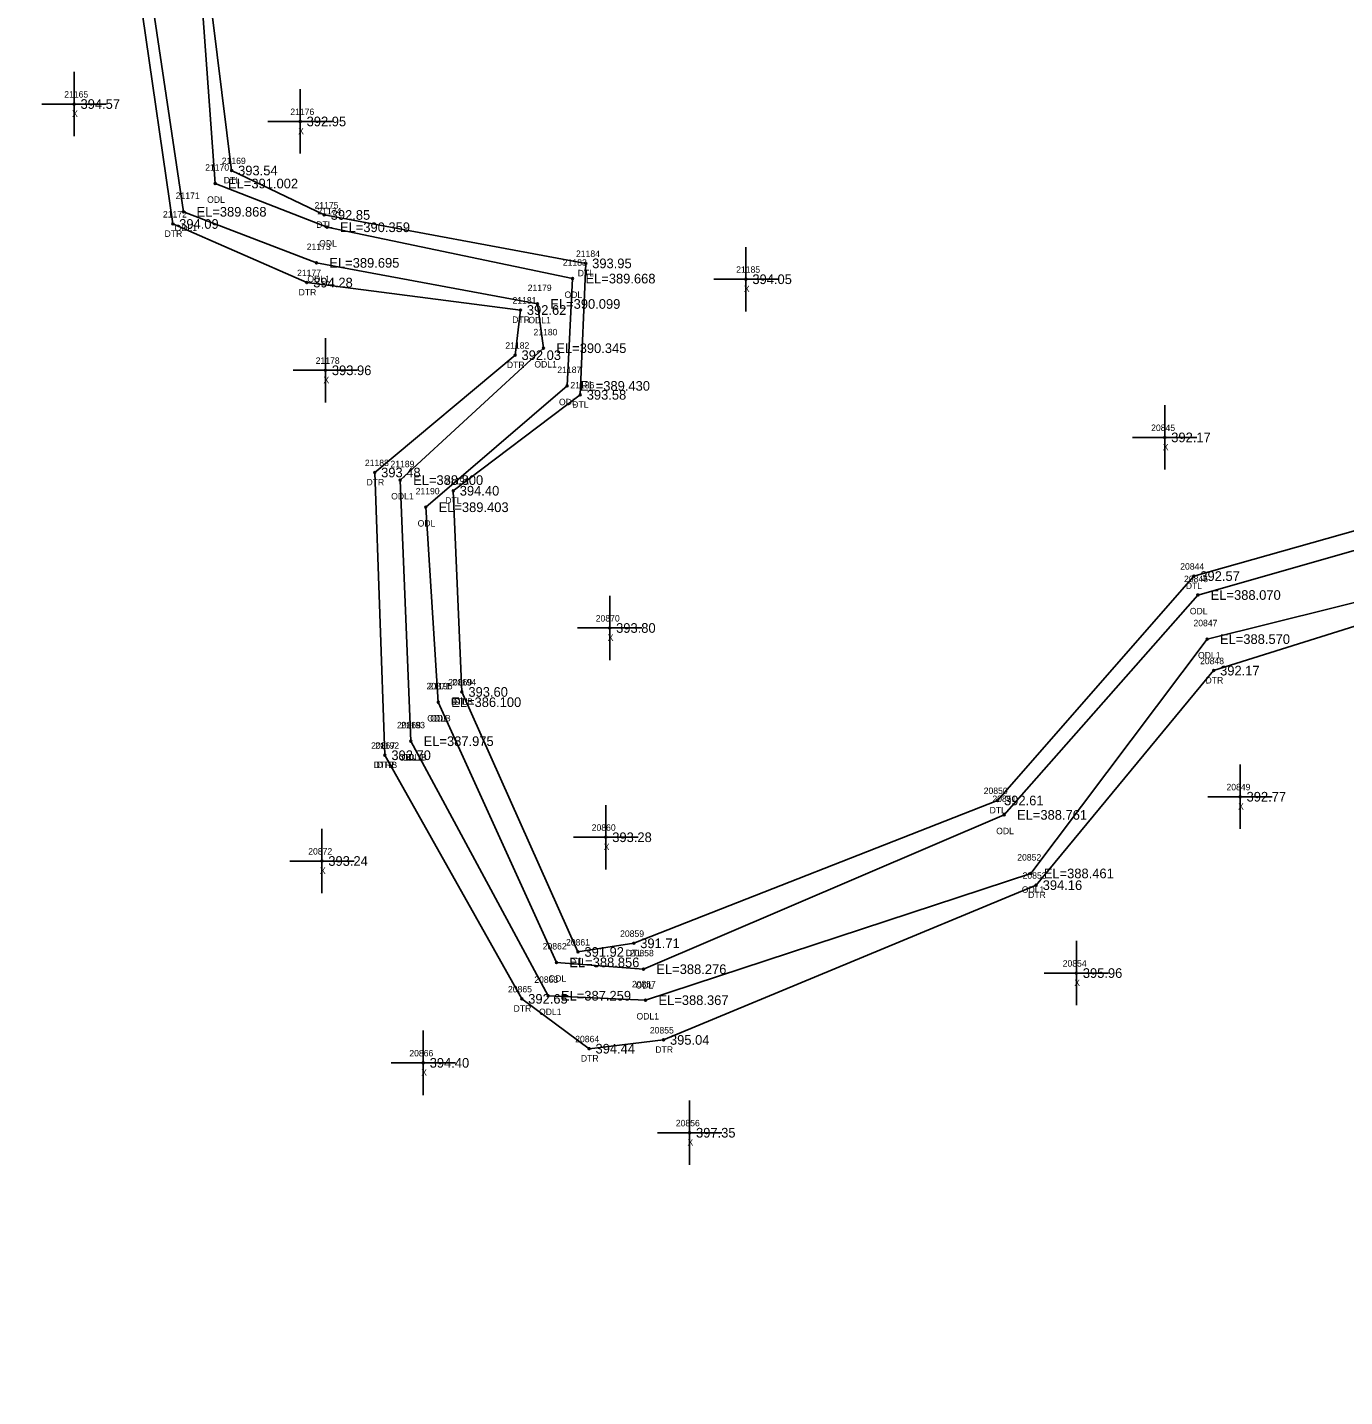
# Model space of a CAD drawing. Extents: x 2186623 to 2187804, y 1079975 to 1082766.
# Drawn here: x 2186677.8 to 2186882.3, y 1082143.2 to 1082355.8 of the extents above; entities that cross this region are included whole.
import ezdxf

# ---------------------------------------------------------------- set-up
doc = ezdxf.new("R2010")
doc.units = 0
for name, color, linetype in [('RD_EX_H2O', 7, 'Continuous'), ('RD_EX_H2O_txCode', 7, 'Continuous'), ('RD_EX_Misc', 7, 'Continuous'), ('RD_EX_Misc_txCode', 7, 'Continuous'), ('RD_EX_TX_H2O_ELEV', 7, 'Continuous'), ('RD_EX_TX_Misc_ELEV', 7, 'Continuous'), ('RD_SMD_Locator', 7, 'Continuous')]:
    doc.layers.add(name, color=color, linetype=linetype)

msp = doc.modelspace()

# ---------------------------------------------------------------- linework, layer by layer
at = {"layer": 'RD_EX_H2O'}
for points in [[(2186739.64, 1082480.93), (2186736.71, 1082447.69), (2186732.47, 1082424.03), (2186725.92, 1082418.58), (2186690.61, 1082404.71), (2186677.78, 1082374.64), (2186695.63, 1082357.86), (2186700.35, 1082325.32), (2186721.17, 1082316.22), (2186754.34, 1082311.96), (2186753.51, 1082304.95), (2186731.71, 1082286.73), (2186733.3, 1082242.83)], [(2186741.85, 1082481.81), (2186738.4, 1082447.71), (2186735.76, 1082423.47), (2186724.6, 1082415.76), (2186694.66, 1082403.51), (2186678.83, 1082375.47), (2186697.14, 1082359.85), (2186702.04, 1082327.21), (2186722.67, 1082319.28), (2186756.98, 1082312.9), (2186757.92, 1082306.03), (2186735.68, 1082285.55), (2186737.31, 1082245.01)], [(2186705.73, 1082363.74), (2186709.5, 1082333.62), (2186723.88, 1082326.72), (2186764.48, 1082319.2), (2186763.64, 1082298.79), (2186743.92, 1082283.9), (2186745.26, 1082252.66)], [(2186704.76, 1082361.57), (2186706.94, 1082331.6), (2186724.32, 1082324.81), (2186762.44, 1082316.84), (2186761.58, 1082300.18), (2186739.63, 1082281.34), (2186741.59, 1082251.07)], [(2187032.54, 1082143.86), (2187021.05, 1082170.12), (2187013.16, 1082184.18), (2187005.63, 1082181.14), (2186996.48, 1082171.24), (2186991.14, 1082183.58), (2186995.14, 1082195), (2187001.03, 1082204.01), (2186999.73, 1082212.87), (2186999.73, 1082212.87), (2186982.72, 1082231.52), (2186959.75, 1082237.17), (2186938.86, 1082276.61), (2186907.09, 1082284.24), (2186858.92, 1082270.65), (2186828.44, 1082235.81), (2186771.94, 1082213.63), (2186763.28, 1082212.29), (2186745.26, 1082252.66)], [(2187022.54, 1082146.29), (2187012.53, 1082167.68), (2187008.73, 1082175.03), (2186995.03, 1082168.62), (2186987.32, 1082182.39), (2186991.15, 1082195.27), (2186992.6, 1082209.25), (2186992.6, 1082209.25), (2186979.71, 1082224.86), (2186956.17, 1082235.38), (2186936.47, 1082274.8), (2186908.13, 1082281.54), (2186859.53, 1082267.71), (2186829.46, 1082233.57), (2186773.45, 1082209.61), (2186759.94, 1082210.67), (2186741.59, 1082251.07)], [(2186982.5, 1082143.25), (2186991.01, 1082149.11), (2186994.56, 1082156.71), (2186997.86, 1082162.51), (2186992.13, 1082163.36), (2186982.55, 1082180.9), (2186984.17, 1082195.73), (2186986.36, 1082206.07), (2186986.36, 1082206.07), (2186977.15, 1082219.73), (2186950.81, 1082232.69), (2186932.48, 1082271.78), (2186909.7, 1082272.95), (2186860.97, 1082260.86), (2186833.61, 1082224.48), (2186773.78, 1082204.8), (2186758.64, 1082205.49), (2186737.31, 1082245.01)], [(2186980.12, 1082202.9), (2186976.01, 1082217.72), (2186947.23, 1082230.9), (2186929.69, 1082269.67), (2186910.3, 1082271.15), (2186861.99, 1082255.97), (2186834.44, 1082222.66), (2186776.56, 1082198.63), (2186765, 1082197.27), (2186754.55, 1082205.01), (2186733.3, 1082242.83)]]:
    msp.add_lwpolyline(points, dxfattribs=at)
at = {"layer": 'RD_EX_Misc'}
for p, q in [((2186685.03, 1082338.94), (2186685.03, 1082348.94)), ((2186720.14, 1082336.24), (2186720.14, 1082346.24)), ((2186680.03, 1082343.94), (2186690.03, 1082343.94)), ((2186715.14, 1082341.24), (2186725.14, 1082341.24)), ((2186789.36, 1082311.74), (2186789.36, 1082321.74)), ((2186784.36, 1082316.74), (2186794.36, 1082316.74)), ((2186724.06, 1082297.6), (2186724.06, 1082307.6)), ((2186719.06, 1082302.6), (2186729.06, 1082302.6)), ((2186854.4, 1082287.18), (2186854.4, 1082297.18)), ((2186849.4, 1082292.18), (2186859.4, 1082292.18)), ((2186768.2, 1082257.59), (2186768.2, 1082267.59)), ((2186763.2, 1082262.59), (2186773.2, 1082262.59)), ((2186866.1, 1082231.39), (2186866.1, 1082241.39)), ((2186861.1, 1082236.39), (2186871.1, 1082236.39)), ((2186767.6, 1082225.1), (2186767.6, 1082235.1)), ((2186723.51, 1082221.41), (2186723.51, 1082231.41)), ((2186762.6, 1082230.1), (2186772.6, 1082230.1)), ((2186718.51, 1082226.41), (2186728.51, 1082226.41)), ((2186840.67, 1082204.01), (2186840.67, 1082214.01)), ((2186835.67, 1082209.01), (2186845.67, 1082209.01)), ((2186739.25, 1082190.07), (2186739.25, 1082200.07)), ((2186734.25, 1082195.07), (2186744.25, 1082195.07)), ((2186780.61, 1082179.22), (2186780.61, 1082189.22)), ((2186775.61, 1082184.22), (2186785.61, 1082184.22))]:
    msp.add_line(p, q, dxfattribs=at)
at = {"layer": 'RD_SMD_Locator'}
for centre in [(2186685.03, 1082343.94), (2186720.14, 1082341.24), (2186709.5, 1082333.62), (2186706.94, 1082331.6), (2186702.04, 1082327.21), (2186723.88, 1082326.72), (2186700.35, 1082325.32), (2186724.32, 1082324.81), (2186722.67, 1082319.28), (2186764.48, 1082319.2), (2186721.17, 1082316.22), (2186762.44, 1082316.84), (2186789.36, 1082316.74), (2186754.34, 1082311.96), (2186756.98, 1082312.9), (2186757.92, 1082306.03), (2186753.51, 1082304.95), (2186724.06, 1082302.6), (2186761.58, 1082300.18), (2186763.64, 1082298.79), (2186854.4, 1082292.18), (2186731.71, 1082286.73), (2186735.68, 1082285.55), (2186743.92, 1082283.9), (2186739.63, 1082281.34), (2186858.92, 1082270.65), (2186859.53, 1082267.71), (2186768.2, 1082262.59), (2186860.97, 1082260.86), (2186861.99, 1082255.97), (2186745.26, 1082252.66), (2186745.26, 1082252.66), (2186741.59, 1082251.07), (2186741.59, 1082251.07), (2186737.31, 1082245.01), (2186737.31, 1082245.01), (2186733.3, 1082242.83), (2186733.3, 1082242.83), (2186828.44, 1082235.81), (2186866.1, 1082236.39), (2186829.46, 1082233.57), (2186767.6, 1082230.1), (2186723.51, 1082226.41), (2186833.61, 1082224.48), (2186834.44, 1082222.66), (2186763.28, 1082212.29), (2186771.94, 1082213.63), (2186759.94, 1082210.67), (2186773.45, 1082209.61), (2186840.67, 1082209.01), (2186758.64, 1082205.49), (2186754.55, 1082205.01), (2186773.78, 1082204.8), (2186765, 1082197.27), (2186776.56, 1082198.63), (2186739.25, 1082195.07), (2186780.61, 1082184.22)]:
    msp.add_circle(centre, 0.15, dxfattribs=at)

# ---------------------------------------------------------------- texts
at = {"layer": 'RD_EX_H2O_txCode'}
for s, p in [('21169', (2186707.97, 1082334.62)), ('21170', (2186705.39, 1082333.6)), ('DTL', (2186708.26, 1082331.62)), ('21171', (2186700.81, 1082329.21)), ('ODL', (2186705.69, 1082328.6)), ('21172', (2186698.83, 1082326.32)), ('21175', (2186722.37, 1082327.72)), ('21174', (2186722.81, 1082326.81)), ('ODL1', (2186700.63, 1082324.21)), ('DTL', (2186722.64, 1082324.72)), ('DTR', (2186699.08, 1082323.32)), ('ODL', (2186723.08, 1082321.81)), ('21173', (2186721.16, 1082321.28)), ('21184', (2186762.97, 1082320.2)), ('21177', (2186719.66, 1082317.22)), ('21183', (2186760.93, 1082318.84)), ('DTL', (2186763.24, 1082317.2)), ('ODL1', (2186721.26, 1082316.28)), ('DTR', (2186719.9, 1082314.22)), ('21181', (2186753.11, 1082312.96)), ('21179', (2186755.47, 1082314.9)), ('ODL', (2186761.19, 1082313.84)), ('DTR', (2186753.07, 1082309.96)), ('ODL1', (2186755.57, 1082309.9)), ('21180', (2186756.37, 1082308.03)), ('21182', (2186752, 1082305.95)), ('DTR', (2186752.24, 1082302.95)), ('ODL1', (2186756.51, 1082303.03)), ('21187', (2186760.07, 1082302.18)), ('21186', (2186762.1, 1082299.79)), ('ODL', (2186760.33, 1082297.18)), ('DTL', (2186762.39, 1082296.79)), ('21188', (2186730.19, 1082287.73)), ('21189', (2186734.16, 1082287.55)), ('DTR', (2186730.44, 1082284.73)), ('21190', (2186738.07, 1082283.34)), ('21191', (2186742.69, 1082284.9)), ('ODL1', (2186734.27, 1082282.55)), ('DTL', (2186742.67, 1082281.9)), ('ODL', (2186738.38, 1082278.34)), ('20844', (2186856.8, 1082271.65)), ('20846', (2186857.39, 1082269.71)), ('DTL', (2186857.67, 1082268.65)), ('ODL', (2186858.29, 1082264.71)), ('20847', (2186858.85, 1082262.86)), ('ODL1', (2186859.56, 1082257.86)), ('20848', (2186859.88, 1082256.97)), ('20869', (2186743.12, 1082253.66)), ('21194', (2186743.75, 1082253.66)), ('DTR', (2186860.73, 1082253.97)), ('20871', (2186739.75, 1082253.07)), ('21195', (2186740.08, 1082253.07)), ('DTLB', (2186743.54, 1082250.66)), ('DTL', (2186744.02, 1082250.66)), ('20868', (2186735.17, 1082247.01)), ('21193', (2186735.8, 1082247.01)), ('ODLB', (2186739.87, 1082248.07)), ('ODL', (2186740.34, 1082248.07)), ('20867', (2186731.15, 1082243.83)), ('21192', (2186731.78, 1082243.83)), ('DTRB', (2186731.56, 1082240.83)), ('DTR', (2186732.03, 1082240.83)), ('ODL1B', (2186735.43, 1082242.01)), ('ODL1', (2186735.9, 1082242.01)), ('20850', (2186826.28, 1082236.81)), ('20851', (2186827.63, 1082235.57)), ('DTL', (2186827.2, 1082233.81)), ('ODL', (2186828.22, 1082230.57)), ('20852', (2186831.49, 1082226.48)), ('20853', (2186832.32, 1082223.66)), ('ODL1', (2186832.2, 1082221.48)), ('DTR', (2186833.17, 1082220.66)), ('20861', (2186761.42, 1082213.29)), ('20859', (2186769.82, 1082214.63)), ('20862', (2186757.8, 1082212.67)), ('DTL', (2186770.7, 1082211.63)), ('20858', (2186771.33, 1082211.61)), ('DTL', (2186762.03, 1082210.29)), ('20863', (2186756.49, 1082207.49)), ('ODL', (2186758.7, 1082207.67)), ('20857', (2186771.66, 1082206.8)), ('ODL', (2186772.21, 1082206.61)), ('20865', (2186752.41, 1082206.01)), ('DTR', (2186753.28, 1082203.01)), ('ODL1', (2186757.23, 1082202.49)), ('ODL1', (2186772.37, 1082201.8)), ('20864', (2186762.85, 1082198.27)), ('20855', (2186774.44, 1082199.63)), ('DTR', (2186775.29, 1082196.63)), ('DTR', (2186763.73, 1082195.27))]:
    msp.add_text(s, height=1, dxfattribs=at).set_placement(p)
at = {"layer": 'RD_EX_Misc_txCode'}
for s, p in [('21165', (2186683.5, 1082344.94)), ('X', (2186684.72, 1082341.94)), ('21176', (2186718.61, 1082342.24)), ('X', (2186719.83, 1082339.24)), ('21185', (2186787.84, 1082317.74)), ('X', (2186789.04, 1082314.74)), ('21178', (2186722.55, 1082303.6)), ('X', (2186723.75, 1082300.6)), ('20845', (2186852.28, 1082293.18)), ('X', (2186854.09, 1082290.18)), ('20870', (2186766.04, 1082263.59)), ('X', (2186767.89, 1082260.59)), ('20849', (2186863.98, 1082237.39)), ('X', (2186865.78, 1082234.39)), ('20860', (2186765.41, 1082231.1)), ('X', (2186767.28, 1082228.1)), ('20872', (2186721.39, 1082227.41)), ('X', (2186723.2, 1082224.41)), ('20854', (2186838.55, 1082210.01)), ('X', (2186840.35, 1082207.01)), ('20866', (2186737.09, 1082196.07)), ('X', (2186738.94, 1082193.07)), ('20856', (2186778.47, 1082185.22)), ('X', (2186780.29, 1082182.22))]:
    msp.add_text(s, height=1, dxfattribs=at).set_placement(p)
at = {"layer": 'RD_EX_TX_H2O_ELEV'}
for s, p in [('393.54', (2186710.5, 1082332.87)), ('EL=391.002', (2186708.94, 1082330.85)), ('EL=389.868', (2186704.04, 1082326.46)), ('392.85', (2186724.88, 1082325.97)), ('394.09', (2186701.35, 1082324.57)), ('EL=390.359', (2186726.32, 1082324.06)), ('EL=389.695', (2186724.67, 1082318.53)), ('393.95', (2186765.48, 1082318.45)), ('394.28', (2186722.17, 1082315.47)), ('EL=389.668', (2186764.44, 1082316.09)), ('392.62', (2186755.34, 1082311.21)), ('EL=390.099', (2186758.98, 1082312.15)), ('392.03', (2186754.51, 1082304.2)), ('EL=390.345', (2186759.92, 1082305.28)), ('EL=389.430', (2186763.58, 1082299.43)), ('393.58', (2186764.64, 1082298.04)), ('393.48', (2186732.71, 1082285.98)), ('EL=388.800', (2186737.68, 1082284.8)), ('394.40', (2186744.92, 1082283.15)), ('EL=389.403', (2186741.63, 1082280.59)), ('392.57', (2186859.92, 1082269.9)), ('EL=388.070', (2186861.53, 1082266.96)), ('EL=388.570', (2186862.97, 1082260.11)), ('392.17', (2186862.99, 1082255.22)), ('393.60', (2186746.26, 1082251.91)), ('393.60', (2186746.26, 1082251.91)), ('EL=386.100', (2186743.59, 1082250.32)), ('EL=386.100', (2186743.59, 1082250.32)), ('EL=387.975', (2186739.31, 1082244.26)), ('EL=387.975', (2186739.31, 1082244.26)), ('392.70', (2186734.3, 1082242.08)), ('392.70', (2186734.3, 1082242.08)), ('392.61', (2186829.44, 1082235.06)), ('EL=388.761', (2186831.46, 1082232.82)), ('EL=388.461', (2186835.61, 1082223.73)), ('394.16', (2186835.44, 1082221.91)), ('391.71', (2186772.94, 1082212.88)), ('391.92', (2186764.28, 1082211.54)), ('EL=388.856', (2186761.94, 1082209.92)), ('EL=388.276', (2186775.45, 1082208.86)), ('392.65', (2186755.55, 1082204.26)), ('EL=387.259', (2186760.64, 1082204.74)), ('EL=388.367', (2186775.78, 1082204.05)), ('395.04', (2186777.56, 1082197.88)), ('394.44', (2186766, 1082196.52))]:
    msp.add_text(s, height=1.5, dxfattribs=at).set_placement(p)
at = {"layer": 'RD_EX_TX_Misc_ELEV'}
for s, p in [('394.57', (2186686.03, 1082343.19)), ('392.95', (2186721.14, 1082340.49)), ('394.05', (2186790.36, 1082315.99)), ('393.96', (2186725.06, 1082301.85)), ('392.17', (2186855.4, 1082291.43)), ('393.80', (2186769.2, 1082261.84)), ('392.77', (2186867.1, 1082235.64)), ('393.28', (2186768.6, 1082229.35)), ('393.24', (2186724.51, 1082225.66)), ('395.96', (2186841.67, 1082208.26)), ('394.40', (2186740.25, 1082194.32)), ('397.35', (2186781.61, 1082183.47))]:
    msp.add_text(s, height=1.5, dxfattribs=at).set_placement(p)

doc.saveas('drawing.dxf')
